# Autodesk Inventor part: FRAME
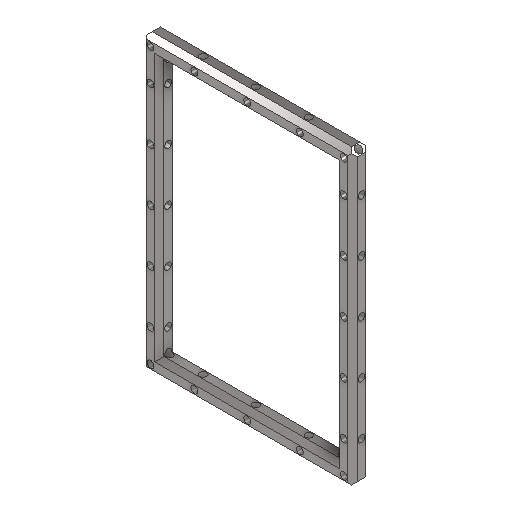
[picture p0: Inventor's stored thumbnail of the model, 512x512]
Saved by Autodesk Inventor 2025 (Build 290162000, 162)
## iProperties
Created: 2025-03
Part Number: FRAME
Material: Stainless Steel
Document SubType Name: Modeling
Designer: dansp
Density: 8 g/cm^3
Appearance: Semi-Polished
Mass: 1137.89 g
Surface Area: 459.941 cm^2
Volume: 142.236 cm^3
Author: dansp
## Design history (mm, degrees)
sketch "Sketch1"
  geometry: L1 (0, 175)-(0, -175) reference; L2 (-126, 0)-(126, 0) reference; L3 (90, -125)-(-90, -125); L4 (-90, -125)-(-90, 125); L5 (-90, 125)-(90, 125); L6 (90, 125)-(90, -125); L7 (90, -125)-(-90, 125); L8 (-90, -125)-(90, 125); L9 (75, 110)-(-75, 110); L10 (-75, 110)-(-75, -110); L11 (-75, -110)-(75, -110); L12 (75, -110)-(75, 110); 1 further point
  constraints: 20 end point, 4 parallel, 2 midpoint, 2 perpendicular, 1 horizontal, 3 other
  dimensions: "d0" = 180 distance between parallel lines of L6 L4; "d1" = 250 distance between parallel lines of L3 L5; "d2" = 15 distance between parallel lines of L5 L9
extrude "Extrusion1" new body sketch "Sketch1" stored distance "d3" = 15; taper "d4" = 0 deg
chamfer "Chamfer1" distance "d5" = 4; stored, may be unused: second distance "d6" = 2, angle "d7" = 45 deg
sketch "Sketch4"
  geometry: L1 (-126, 0)-(126, 0) reference; L2 (0, 175)-(0, -175) reference; L3 (-90, -125)-(-90, 125) reference; L4 (-75, 110)-(-75, -110) reference; L5 (75, -110)-(75, 110) reference; L6 (90, 125)-(90, -125) reference; L7 (90, -125)-(-90, -125) reference; L8 (-75, -110)-(75, -110) reference; L9 (75, 110)-(-75, 110) reference; L10 (-90, 125)-(90, 125) reference; C1 r 3 at (-82.5, 0); C2 r 3 at (-82.5, 45); C3 r 3 at (-82.5, 90); C4 r 3 at (-82.5, -90); C5 r 3 at (-82.5, -45); C6 r 3 at (82.5, 90); C7 r 3 at (82.5, 45); C8 r 3 at (82.5, 0); C9 r 3 at (82.5, -45); C10 r 3 at (82.5, -90); C11 r 3 at (0, 117.5); C12 r 3 at (-45, 117.5); C13 r 3 at (45, 117.5); C14 r 3 at (45, -117.5); C15 r 3 at (0, -117.5); C16 r 3 at (-45, -117.5); C17 r 3 at (-82.5, 117.5); C18 r 3 at (82.5, 117.5); C19 r 3 at (-82.5, -117.5); C20 r 3 at (82.5, -117.5); 9 further points
  constraints: 20 centre point, 14 symmetric about line, 2 point on line, 14 other
  dimensions: "d14" = 6 diameter of C1; "d15" = 15 distance between parallel lines of L4 L3 (derived); "d16" = 7.5 distance from line of C1.centre L3 (= 0.5 x d15); "d17" = 6 diameter of C2; "d18" = 6 diameter of C3; "d19" = 20 distance from line of C3.centre L9; "d20" = 45 distance of C2.centre C3.centre; "d21" = 6 diameter of C11; "d22" = 7.5 distance from line of L10 C11.centre (= d16); "d23" = 6 diameter of C12; "d24" = 45 distance of C11.centre C12.centre; "d31" = 6 diameter of C17; "d32" = 7.5 distance from line of C17.centre L9 (= d22)
extrude "Extrusion3" cut sketch "Sketch4" extent not by distance; stored distance "d25" = 10; taper "d26" = 0 deg
sketch "Sketch5"
  geometry: L1 (-93, 7.5)-(-87, 7.5) reference; L2 (-87, 0)-(-93, 0) reference; L3 (-48, 7.5)-(-42, 7.5) reference; L4 (-42, 0)-(-48, 0) reference; L5 (-3, 7.5)-(3, 7.5) reference; L6 (3, 0)-(-3, 0) reference; L7 (42, 7.5)-(48, 7.5) reference; L8 (48, 0)-(42, 0) reference; L9 (87, 7.5)-(93, 7.5) reference; L10 (93, 0)-(87, 0) reference; L11 (-42, 0)-(-48, 0) reference; L12 (3, 0)-(-3, 0) reference; L13 (48, 0)-(42, 0) reference; L14 (93, 0)-(87, 0) reference; 6 further points
  constraints: 5 horizontal alignment, 4 midpoint, 1 coincident, 10 other
extrude "Extrusion4" cut sketch "Sketch5" extent not by distance; stored distance "d27" = 0; taper "d28" = 0 deg
sketch "Sketch6"
  geometry: L1 (42, 7.5)-(48, 7.5) reference; L2 (48, 0)-(42, 0) reference; L3 (-3, 7.5)-(3, 7.5) reference; L4 (3, 0)-(-3, 0) reference; L5 (-48, 7.5)-(-42, 7.5) reference; L6 (-42, 0)-(-48, 0) reference; 4 further points
  constraints: 3 horizontal alignment, 2 midpoint, 1 coincident, 6 other
extrude "Extrusion5" cut sketch "Sketch6" extent not by distance; stored distance "d29" = 10; taper "d30" = 0 deg
sketch "Sketch7"
  geometry: L1 (-75, -110)-(75, -110) reference; L2 (90, -125)-(75, -110); L3 (90, 125)-(90, -125) reference; L4 (90, -120.757)-(75, -105.757); L5 (75, -110)-(75, 110) reference; L6 (90, -120.757)-(90, -125); L7 (75, -105.757)-(75, -110); L8 (90, -125)-(75, -110); L9 (75, -105.757)-(75, -110); L10 (90, -120.757)-(90, -125); L11 (90, -120.757)-(94.243, -125); L12 (94.243, -125)-(92.121, -127.121); L13 (92.121, -127.121)-(90, -125); 1 further point
  constraints: 20 end point, 2 collinear, 2 perpendicular, 2 point on line, 1 parallel
  dimensions: "d33" = 6 diameter of L4 L2
revolve "Revolution1" sketch "Sketch7" stored, may be unused: angle "d34" = 360 deg
mirror "Mirror1"
mirror "Mirror2"
chamfer "Chamfer2" distance "d35" = 5; stored, may be unused: second distance "d36" = 2, angle "d37" = 45 deg
body "Solid1"
node "Projected Loop1"
node "Projected Loop2"
node "Projected Loop3"
node "Projected Loop4"
node "Projected Loop5"
node "Projected Loop6"
node "Projected Loop7"
node "Projected Loop8"
